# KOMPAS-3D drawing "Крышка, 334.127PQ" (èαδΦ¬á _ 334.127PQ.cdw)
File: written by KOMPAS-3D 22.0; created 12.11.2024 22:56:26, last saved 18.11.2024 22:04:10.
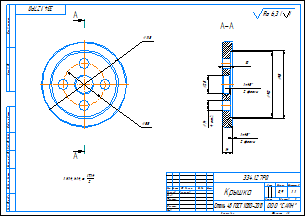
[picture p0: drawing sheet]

Sheet 1: A3, landscape

Document properties: Автор: aleksander.larionov.10@gmail.com; Знак неуказанной шероховатости: 4; Параметр неуказанной шероховатости: Ra 6,3; Масса: 0.895808; Полное имя файла: Крышка _ 334.127PQ.m3d

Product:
- Part/product: Крышка  | designation 334.127PQ
    Материал: Сталь 45 ГОСТ 1050-2013 (density 7810 kg/m3)
    Масса: 0.895808

Title block, sheet 1: Наименование: Крышка; designation: 334.127PQ; Материал: Сталь 45 ГОСТ 1050-2013; Масса: 0,9; Количество листов документа: 1; organisation: ООО "САЙН"; Форматы листов документа: A3; stored path: C:\Мои папки\Работа\Крышки, фланцы\334.127PQ\Сальник _ 334.127PQ.cdw; Разработал: Ларионов

Views: Вид 1, Сверху, Разрез А-А
Referenced files in C:\Мои папки\Работа\Крышки, фланцы\334.127PQ\: Сальник _ 334.127PQ.m3d, Крышка _ 334.127PQ.m3d
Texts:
  Ra 6,3
  Ra 6,3 ( )
Dimensions and other numbers on the sheet: 118; 58; 334.127PQ; 90; 95; 14; 1; 2 фаски; 4 отв.; 25; 10; 1 H14, h14,    IT14 2 .; 1:1; 0,9; 334.127PQ Крышка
